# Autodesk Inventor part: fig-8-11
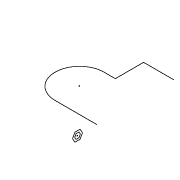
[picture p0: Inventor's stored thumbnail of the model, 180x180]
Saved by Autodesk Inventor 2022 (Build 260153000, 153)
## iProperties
Created: 2004-05
Part Number: fig-8-11
Document SubType Name: Modeling
Designer: CADCIM Technologies
Manufacturer: Standard
Standards Organization: Custom
Density: 1 g/cm^3
Material: Generic
Appearance: Default
Author: CADCIM Technologies
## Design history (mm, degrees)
sketch "Sketch1"
  geometry: L1 (-42.583, 3.219)-(-90.066, 3.219); L2 (-90.066, 58.92)-(-77.282, 58.92); L3 (-77.282, 58.92)-(-77.282, 91.063); L4 (-77.282, 91.063)-(-42.583, 91.063); A1 r 27.851 centre (-90.066, 31.07) between (-90.066, 58.92) and (-90.066, 3.219)
  constraints: 8 end point, 2 parallel, 2 point on circle, 2 tangent, 1 centre point, 1 perpendicular
workplane "Work Plane2"
body "Solid1"
sketch "Sketch2"
  geometry: L1 (16.303, 0)-(19.151, 4.934); L2 (19.151, 4.934)-(24.849, 4.934); L3 (24.849, 4.934)-(27.697, 0); L4 (27.697, 0)-(24.849, -4.934); L5 (24.849, -4.934)-(19.151, -4.934); L6 (19.151, -4.934)-(16.303, 0); L7 (18.744, 0)-(20.372, 2.819); L8 (20.372, 2.819)-(23.628, 2.819); L9 (23.628, 2.819)-(25.256, 0); L10 (25.256, 0)-(23.628, -2.819); L11 (23.628, -2.819)-(20.372, -2.819); L12 (20.372, -2.819)-(18.744, 0); 2 further points
  constraints: 24 end point, 1 coincident, 22 other
